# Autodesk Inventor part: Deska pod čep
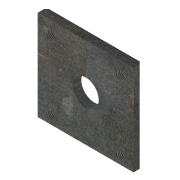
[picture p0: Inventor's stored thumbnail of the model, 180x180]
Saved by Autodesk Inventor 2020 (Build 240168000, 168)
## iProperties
Created: 2025-03
Part Number: Deska pod čep
Material: Ocel
Document SubType Name: Modeling
Designer: doma
Density: 7.85 g/cm^3
Appearance: Plech
Mass: 817.365 g
Surface Area: 273.17 cm^2
Volume: 104.123 cm^3
Author: doma
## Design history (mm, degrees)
sketch "Náčrt1"
  geometry: L1 (0, 0)-(110, 0); L2 (110, 0)-(110, 104); L3 (110, 104)-(0, 104); L4 (0, 104)-(0, 0)
  constraints: 8 end point, 2 parallel, 1 horizontal, 1 perpendicular
  dimensions: "d0" = 110 distance of L3.end L2.end; "d1" = 104 distance of L2.end L1.end
extrude "Vysunutí1" new body sketch "Náčrt1" distance "d2" = 10; taper "d3" = 0 deg
sketch "Náčrt2"
  geometry: C1 r 6.75 at (95, 89) reference; C2 r 6.75 at (15, 89) reference; C3 r 6.75 at (95, 9) reference; C4 r 6.75 at (15, 9) reference; 5 further points
  constraints: 4 coincident
hole "Díra1" sketch "Náčrt2" at (15, 89), (95, 89), (95, 9), (15, 9) diameter "d4" = 10.106; stored, may be unused: countersink angle "d8" = 90 deg, drill point angle "d10" = 118 deg; dims "d5" = 24, "d6" = 4, "d7" = 2, "d9" = 32.3
sketch "Náčrt3"
  geometry: L1 (0, 104)-(0, 0) reference; L2 (110, 0)-(110, 104) reference; L3 (0, 104)-(110, 0); L4 (0, 0)-(110, 0) reference; L5 (0, 0)-(110, 104); C1 r 15 at (55, 52)
  constraints: 4 end point, 1 centre point, 1 midpoint
  dimensions: "d11" = 30 diameter of C1
extrude "Vysunutí2" cut sketch "Náčrt3" extent not by distance; stored distance "d12" = 0; taper "d13" = 0 deg
chamfer "Zkosení1" distance "d14" = 3; stored, may be unused: second distance "d15" = 2, angle "d16" = 45 deg
node "Těleso1"
node "Referenční1"
node "Referenční2"
node "Referenční3"
node "Referenční4"
